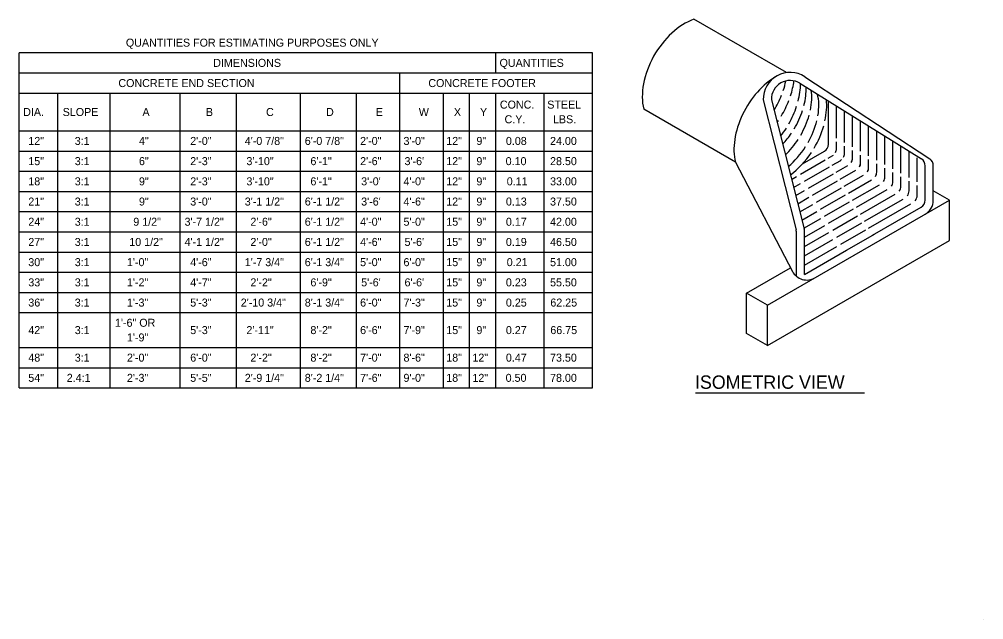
# Model space of a CAD drawing. Extents: x 1 to 8.2, y -2.1 to 8.1.
# Drawn here: x 1.01 to 8.24, y -2.08 to 2.42 of the extents above; entities that cross this region are included whole.
import ezdxf

# ---------------------------------------------------------------- set-up
doc = ezdxf.new("R2010")
doc.units = 0
for name, color, linetype in [('DETL-LINE', 7, 'Continuous'), ('DETL-NOTE', 7, 'Continuous'), ('DETL-TITL', 7, 'Continuous'), ('TTLB-TEXT', 7, 'Continuous')]:
    doc.layers.add(name, color=color, linetype=linetype)

msp = doc.modelspace()

# ---------------------------------------------------------------- linework, layer by layer
at = {"layer": 'DETL-LINE'}
for p, q in [((6.7601, 2.0197), (6.0671, 2.4199)), ((6.8988, 1.9885), (7.8346, 1.3727)), ((6.8624, 1.9399), (7.7728, 1.3725)), ((6.5855, 1.8158), (6.8329, 0.8397)), ((6.6478, 1.8168), (6.8935, 0.8473)), ((6.3782, 1.349), (5.6908, 1.7458)), ((7.0753, 1.4823), (7.0753, 1.8071)), ((7.136, 1.5271), (7.136, 1.7694)), ((7.1953, 1.4951), (7.1953, 1.7324)), ((7.2559, 1.4623), (7.2559, 1.6946)), ((7.3165, 1.4296), (7.3165, 1.6569)), ((7.3771, 1.3968), (7.3771, 1.6191)), ((7.4377, 1.364), (7.4377, 1.5813)), ((7.4983, 1.3313), (7.4983, 1.5435)), ((7.136, 1.4488), (7.136, 1.4996)), ((7.1953, 1.413), (7.1953, 1.4675)), ((7.5589, 1.2985), (7.5589, 1.5058)), ((7.6195, 1.2658), (7.6195, 1.468)), ((6.8819, 1.3356), (7.045, 1.4298)), ((7.0736, 1.3778), (7.1098, 1.3987)), ((7.2559, 1.3781), (7.2559, 1.4348)), ((7.3165, 1.3431), (7.3165, 1.402)), ((7.6801, 1.233), (7.6801, 1.4302)), ((7.7407, 1.2003), (7.7407, 1.3817)), ((6.3782, 1.349), (6.8061, 0.5295)), ((6.8652, 1.2575), (7.0521, 1.3654)), ((6.8955, 1.205), (7.0824, 1.3129)), ((7.1039, 1.3253), (7.1674, 1.362)), ((7.1342, 1.2728), (7.221, 1.323)), ((7.3771, 1.3081), (7.3771, 1.3692)), ((7.4377, 1.2731), (7.4377, 1.3365)), ((7.4983, 1.2381), (7.4983, 1.3037)), ((7.8013, 1.0631), (7.8013, 1.3211)), ((7.8619, 1.0631), (7.8619, 1.322)), ((6.7992, 1.2194), (6.8363, 1.2408)), ((6.9258, 1.1525), (7.1127, 1.2604)), ((7.1645, 1.2204), (7.2801, 1.2871)), ((7.1948, 1.1679), (7.3392, 1.2512)), ((7.5589, 1.2031), (7.5589, 1.271)), ((7.6195, 1.1606), (7.6195, 1.2382)), ((6.8147, 1.1583), (6.8666, 1.1883)), ((6.9561, 1.1), (7.143, 1.2079)), ((7.2251, 1.1154), (7.3983, 1.2154)), ((7.2554, 1.0629), (7.4574, 1.1795)), ((7.6801, 1.1331), (7.6801, 1.2055)), ((7.7407, 1.0981), (7.7407, 1.1727)), ((6.8301, 1.0973), (6.8969, 1.1358)), ((6.8456, 1.0362), (6.9294, 1.0846)), ((6.9864, 1.0475), (7.1733, 1.1554)), ((7.0167, 0.995), (7.2036, 1.1029)), ((7.2858, 1.0104), (7.5165, 1.1436)), ((7.3161, 0.9579), (7.5756, 1.1078)), ((7.9831, 1.0631), (7.8619, 1.1331)), ((6.6185, 0.2753), (7.9831, 1.0631)), ((6.8611, 0.9752), (6.9575, 1.0308)), ((7.047, 0.9426), (7.2339, 1.0505)), ((7.3464, 0.9054), (7.6347, 1.0719)), ((7.3767, 0.8529), (7.6938, 1.036)), ((7.9831, 0.7601), (7.9831, 1.0631)), ((6.8765, 0.9141), (6.9878, 0.9784)), ((7.0773, 0.8901), (7.2642, 0.998)), ((7.1076, 0.8376), (7.2945, 0.9455)), ((7.407, 0.8005), (7.771, 1.0106)), ((6.892, 0.8531), (7.0181, 0.9259)), ((6.8972, 0.7861), (7.0484, 0.8734)), ((7.1379, 0.7851), (7.3248, 0.893)), ((6.8366, 0.492), (6.8366, 0.8099)), ((6.8972, 0.7161), (7.0787, 0.8209)), ((6.8972, 0.506), (6.8972, 0.8175)), ((7.1682, 0.7326), (7.3551, 0.8405)), ((7.1985, 0.6801), (7.4215, 0.8089)), ((6.6185, -0.0278), (7.9831, 0.7601)), ((6.8972, 0.6461), (7.109, 0.7684)), ((6.8972, 0.5761), (7.1393, 0.7159)), ((6.8972, 0.5061), (7.2123, 0.6881)), ((6.461, 0.3662), (6.7917, 0.5571)), ((6.461, 0.0631), (6.461, 0.3662)), ((6.6185, 0.2753), (6.461, 0.3662)), ((6.6185, -0.0278), (6.6185, 0.2753)), ((6.6185, -0.0278), (6.461, 0.0631))]:
    msp.add_line(p, q, dxfattribs=at)
for centre, radius, start, end in [((6.7881, 1.8207), 0.201, 56.59286, 181.65186), ((6.7881, 1.8207), 0.1404, 58.06793, 181.61307), ((7.0147, 1.4823), 0.0606, 299.99912, 0), ((7.0753, 1.4488), 0.0606, 332.89348, 0), ((7.0753, 1.4488), 0.0606, 299.99908, 309.25003), ((7.1347, 1.413), 0.0606, 332.68419, 0), ((7.1953, 1.3781), 0.0606, 328.0844, 0), ((7.1953, 1.3781), 0.0606, 331.23284, 0), ((7.1347, 1.413), 0.0606, 300.00015, 310.83611), ((7.2559, 1.3431), 0.0606, 329.78323, 0), ((7.2559, 1.3431), 0.0606, 332.70174, 0), ((7.3165, 1.3081), 0.0606, 328.3347, 0), ((7.3165, 1.3081), 0.0606, 333.71161, 0), ((7.7407, 1.3211), 0.0606, 0, 58.06766), ((7.8013, 1.322), 0.0606, 0, 56.65326), ((7.3771, 1.2731), 0.0606, 326.88514, 0), ((7.4377, 1.2381), 0.0606, 325.43445, 0), ((7.4983, 1.2031), 0.0606, 323.98242, 0), ((7.5589, 1.1681), 0.0606, 322.52658, 0), ((7.6195, 1.1331), 0.0606, 321.06707, 0), ((7.6801, 1.0981), 0.0606, 319.60235, 0), ((7.7407, 1.0631), 0.0606, 300.00022, 0), ((7.7407, 1.0631), 0.1212, 300.00001, 0), ((6.7154, 0.8099), 0.1212, 0, 14.21998), ((6.776, 0.8175), 0.1212, 0, 14.21998), ((6.776, 0.8175), 0.1212, 0, 14.21988), ((6.8366, 0.8251), 0.0606, 0, 14.21976), ((6.8366, 0.8251), 0.0606, 0, 14.22013), ((6.9136, 0.5856), 0.1212, 207.57459, 300.00006)]:
    msp.add_arc(centre, radius, start, end, dxfattribs=at)
for centre, major_axis, ratio, start_param, end_param in [((6.0276, 2.0041), (0.2344, 0.406), 0.631984, 0.629642, 2.560999), ((6.715, 1.6072), (0.2344, 0.406), 0.631984, 0.821883, 2.560999), ((6.4207, 1.9016), (0.2344, 0.406), 0.631984, 5.025988, 5.191832), ((6.4737, 1.8565), (0.2344, 0.406), 0.631984, 5.038097, 5.299324), ((6.5188, 1.777), (0.2344, 0.406), 0.631984, 5.127423, 5.442529), ((6.6195, 1.7239), (0.2041, 0.3536), 0.57735, 5.165824, 5.562158), ((6.6619, 1.6656), (0.2041, 0.3536), 0.57735, 5.229741, 5.672427), ((6.4207, 1.9016), (0.2344, 0.406), 0.631984, 4.673011, 4.94344), ((6.4737, 1.8565), (0.2344, 0.406), 0.631984, 4.673973, 4.955193), ((6.715, 1.6072), (0.2041, 0.3536), 0.57735, 5.277374, 5.774846), ((6.715, 1.6072), (0.2344, 0.406), 0.631984, 5.180718, 5.567902), ((6.5188, 1.777), (0.2344, 0.406), 0.631984, 4.730463, 5.041423), ((6.6195, 1.7239), (0.2041, 0.3536), 0.57735, 4.689494, 5.065774), ((6.6619, 1.6656), (0.2041, 0.3536), 0.57735, 4.720629, 5.126264), ((6.4737, 1.8565), (0.2344, 0.406), 0.631984, 4.556453, 4.594713), ((6.5188, 1.777), (0.2344, 0.406), 0.631984, 4.489588, 4.650718), ((6.715, 1.6072), (0.2041, 0.3536), 0.57735, 4.733166, 5.170925), ((6.715, 1.6072), (0.2344, 0.406), 0.631984, 4.6979, 5.092436), ((6.6195, 1.7239), (0.2041, 0.3536), 0.57735, 4.329229, 4.598301), ((6.6619, 1.6656), (0.2041, 0.3536), 0.57735, 4.254318, 4.629176), ((6.715, 1.6072), (0.2041, 0.3536), 0.57735, 4.13577, 4.641583), ((6.715, 1.6072), (0.2344, 0.406), 0.631984, 4.101477, 4.618466)]:
    msp.add_ellipse(centre, major_axis=major_axis, ratio=ratio, start_param=start_param, end_param=end_param, dxfattribs=at)
at = {"layer": 'DETL-NOTE'}
for p, q in [((1.0094, -0.3449), (1.0094, 2.1688)), ((5.307, 2.1688), (1.0094, 2.1688)), ((4.5809, 2.0173), (4.5809, 2.1688)), ((5.307, -0.3449), (5.307, 2.1688)), ((1.0094, 2.0173), (5.307, 2.0173)), ((3.8636, -0.3449), (3.8636, 2.0173)), ((1.0094, 1.8658), (5.307, 1.8658)), ((1.2974, -0.3449), (1.2974, 1.8658)), ((1.69, -0.3449), (1.69, 1.8658)), ((2.216, -0.3449), (2.216, 1.8658)), ((2.6387, -0.3449), (2.6387, 1.8658)), ((3.1184, -0.3449), (3.1184, 1.8658)), ((3.5385, -0.3449), (3.5385, 1.8658)), ((4.1886, -0.3449), (4.1886, 1.8658)), ((4.3848, -0.3449), (4.3848, 1.8658)), ((4.5809, -0.3449), (4.5809, 1.8658)), ((4.9439, -0.3449), (4.9439, 1.8658)), ((1.0094, 1.5833), (5.307, 1.5833)), ((1.0094, 1.4318), (5.307, 1.4318)), ((1.0094, 1.2803), (5.307, 1.2803)), ((1.0094, 1.1288), (5.307, 1.1288)), ((1.0094, 0.9772), (5.307, 0.9772)), ((1.0094, 0.8257), (5.307, 0.8257)), ((1.0094, 0.6742), (5.307, 0.6742)), ((1.0094, 0.5227), (5.307, 0.5227)), ((1.0094, 0.3712), (5.307, 0.3712)), ((1.0094, 0.2197), (5.307, 0.2197)), ((1.0094, -0.0419), (5.307, -0.0419)), ((1.0094, -0.1934), (5.307, -0.1934)), ((1.0094, -0.3449), (5.307, -0.3449))]:
    msp.add_line(p, q, dxfattribs=at)
at = {"layer": 'DETL-TITL'}
msp.add_line((6.0793, -0.3818), (7.3455, -0.3818), dxfattribs=at)
at = {"layer": 'TTLB-TEXT'}
msp.add_line((8.2397, -2.0831), (8.2397, -2.0831), dxfattribs=at)

# ---------------------------------------------------------------- texts
at = {"layer": 'DETL-NOTE'}
for s, p in [('QUANTITIES FOR ESTIMATING PURPOSES ONLY', (1.8086, 2.2146)), ('DIMENSIONS', (2.4635, 2.063)), ('QUANTITIES', (4.61, 2.063)), ('CONCRETE END SECTION', (1.7524, 1.9115)), ('CONCRETE FOOTER', (4.0761, 1.9115)), ('CONC.', (4.6125, 1.75)), ('STEEL', (4.9677, 1.75)), ('DIA.', (1.0385, 1.6945)), ('SLOPE', (1.3348, 1.6945)), ('A', (1.9329, 1.6945)), ('B', (2.4082, 1.6945)), ('C', (2.8594, 1.6945)), ('D', (3.3093, 1.6945)), ('E', (3.6821, 1.6945)), ('W', (4.0046, 1.6945)), ('X', (4.2678, 1.6945)), ('Y', (4.4632, 1.6945)), ('C.Y.', (4.6475, 1.64)), ('LBS.', (5.0105, 1.64)), ('12"', (1.0771, 1.4775)), ('3:1', (1.4252, 1.4775)), ('4"', (1.9066, 1.4775)), ('2\'-0"', (2.291, 1.4775)), ('4\'-0 7/8"', (2.6998, 1.4775)), ('6\'-0 7/8"', (3.1497, 1.4775)), ('2\'-0"', (3.5647, 1.4775)), ('3\'-0"', (3.8898, 1.4775)), ('12"', (4.2104, 1.4775)), ('9"', (4.4365, 1.4775)), ('0.08', (4.6576, 1.4775)), ('24.00', (4.9887, 1.4775)), ('15"', (1.0771, 1.326)), ('3:1', (1.4252, 1.326)), ('6"', (1.9066, 1.326)), ('2\'-3"', (2.291, 1.326)), ('3\'-10"', (2.7122, 1.326)), ('6\'-1"', (3.1921, 1.326)), ('2\'-6"', (3.5647, 1.326)), ("3'-6'", (3.8976, 1.326)), ('12"', (4.2104, 1.326)), ('9"', (4.4365, 1.326)), ('0.10', (4.6557, 1.326)), ('28.50', (4.9887, 1.326)), ('18"', (1.0771, 1.1745)), ('3:1', (1.4252, 1.1745)), ('9"', (1.9066, 1.1745)), ('2\'-3"', (2.291, 1.1745)), ('3\'-10"', (2.7122, 1.1745)), ('6\'-1"', (3.1921, 1.1745)), ("3'-0'", (3.5725, 1.1745)), ('4\'-0"', (3.8898, 1.1745)), ('12"', (4.2104, 1.1745)), ('9"', (4.4365, 1.1745)), ('0.11', (4.6639, 1.1745)), ('33.00', (4.9887, 1.1745)), ('3\'-1 1/2"', (2.6998, 1.023)), ('6\'-1 1/2"', (3.1497, 1.023)), ('21"', (1.0771, 1.023)), ('3:1', (1.4252, 1.023)), ('9"', (1.9066, 1.023)), ('3\'-0"', (2.291, 1.023)), ("3'-6'", (3.5725, 1.023)), ('4\'-6"', (3.8898, 1.023)), ('12"', (4.2104, 1.023)), ('9"', (4.4365, 1.023)), ('0.13', (4.6576, 1.023)), ('37.50', (4.9887, 1.023)), ('24"', (1.0771, 0.8715)), ('3:1', (1.4252, 0.8715)), ('9 1/2"', (1.8642, 0.8715)), ('3\'-7 1/2"', (2.2486, 0.8715)), ('2\'-6"', (2.7422, 0.8715)), ('6\'-1 1/2"', (3.1497, 0.8715)), ('4\'-0"', (3.5647, 0.8715)), ('5\'-0"', (3.8898, 0.8715)), ('15"', (4.2104, 0.8715)), ('9"', (4.4365, 0.8715)), ('0.17', (4.6576, 0.8715)), ('42.00', (4.9887, 0.8715)), ('27"', (1.0771, 0.72)), ('3:1', (1.4252, 0.72)), ('10 1/2"', (1.8342, 0.72)), ('4\'-1 1/2"', (2.2486, 0.72)), ('2\'-0"', (2.7422, 0.72)), ('6\'-1 1/2"', (3.1497, 0.72)), ('4\'-6"', (3.5647, 0.72)), ("5'-6'", (3.8976, 0.72)), ('15"', (4.2104, 0.72)), ('9"', (4.4365, 0.72)), ('0.19', (4.6576, 0.72)), ('46.50', (4.9887, 0.72)), ('30"', (1.0771, 0.5684)), ('3:1', (1.4252, 0.5684)), ('1\'-0"', (1.8166, 0.5684)), ('4\'-6"', (2.291, 0.5684)), ('1\'-7 3/4"', (2.6998, 0.5684)), ('6\'-1 3/4"', (3.1497, 0.5684)), ('5\'-0"', (3.5647, 0.5684)), ('6\'-0"', (3.8898, 0.5684)), ('15"', (4.2104, 0.5684)), ('9"', (4.4365, 0.5684)), ('0.21', (4.6639, 0.5684)), ('51.00', (4.9887, 0.5684)), ('33"', (1.0771, 0.4169)), ('3:1', (1.4252, 0.4169)), ('1\'-2"', (1.8166, 0.4169)), ('4\'-7"', (2.291, 0.4169)), ('2\'-2"', (2.7422, 0.4169)), ('6\'-9"', (3.1921, 0.4169)), ("5'-6'", (3.5725, 0.4169)), ("6'-6'", (3.8976, 0.4169)), ('15"', (4.2104, 0.4169)), ('9"', (4.4365, 0.4169)), ('0.23', (4.6576, 0.4169)), ('55.50', (4.9887, 0.4169)), ('36"', (1.0771, 0.2654)), ('3:1', (1.4252, 0.2654)), ('1\'-3"', (1.8166, 0.2654)), ('5\'-3"', (2.291, 0.2654)), ('2\'-10 3/4"', (2.6698, 0.2654)), ('8\'-1 3/4"', (3.1497, 0.2654)), ('6\'-0"', (3.5647, 0.2654)), ('7\'-3"', (3.8898, 0.2654)), ('15"', (4.2104, 0.2654)), ('9"', (4.4365, 0.2654)), ('0.25', (4.6576, 0.2654)), ('62.25', (4.9907, 0.2654)), ('1\'-6" OR', (1.727, 0.1139)), ('42"', (1.0771, 0.0589)), ('3:1', (1.4252, 0.0589)), ('5\'-3"', (2.291, 0.0589)), ('2\'-11"', (2.7122, 0.0589)), ('8\'-2"', (3.1921, 0.0589)), ('6\'-6"', (3.5647, 0.0589)), ('7\'-9"', (3.8898, 0.0589)), ('15"', (4.2104, 0.0589)), ('9"', (4.4365, 0.0589)), ('0.27', (4.6576, 0.0589)), ('66.75', (4.9907, 0.0589)), ('1\'-9"', (1.8166, 0.0039)), ('48"', (1.0771, -0.1476)), ('3:1', (1.4252, -0.1476)), ('2\'-0"', (1.8166, -0.1476)), ('6\'-0"', (2.291, -0.1476)), ('2\'-2"', (2.7422, -0.1476)), ('8\'-2"', (3.1921, -0.1476)), ('7\'-0"', (3.5647, -0.1476)), ('8\'-6"', (3.8898, -0.1476)), ('18"', (4.2104, -0.1476)), ('12"', (4.4065, -0.1476)), ('0.47', (4.6576, -0.1476)), ('73.50', (4.9887, -0.1476)), ('54"', (1.0771, -0.2991)), ('2.4:1', (1.3652, -0.2991)), ('2\'-3"', (1.8166, -0.2991)), ('5\'-5"', (2.291, -0.2991)), ('2\'-9 1/4"', (2.6998, -0.2991)), ('8\'-2 1/4"', (3.1497, -0.2991)), ('7\'-6"', (3.5647, -0.2991)), ('9\'-0"', (3.8898, -0.2991)), ('18"', (4.2104, -0.2991)), ('12"', (4.4065, -0.2991)), ('0.50', (4.6557, -0.2991)), ('78.00', (4.9887, -0.2991))]:
    msp.add_text(s, height=0.06, dxfattribs=at).set_placement(p)
at = {"layer": 'DETL-TITL'}
msp.add_text('ISOMETRIC VIEW', height=0.1, dxfattribs=at).set_placement((6.075, -0.3515))

doc.saveas('drawing.dxf')
